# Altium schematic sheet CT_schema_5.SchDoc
size 309 x 315 mm
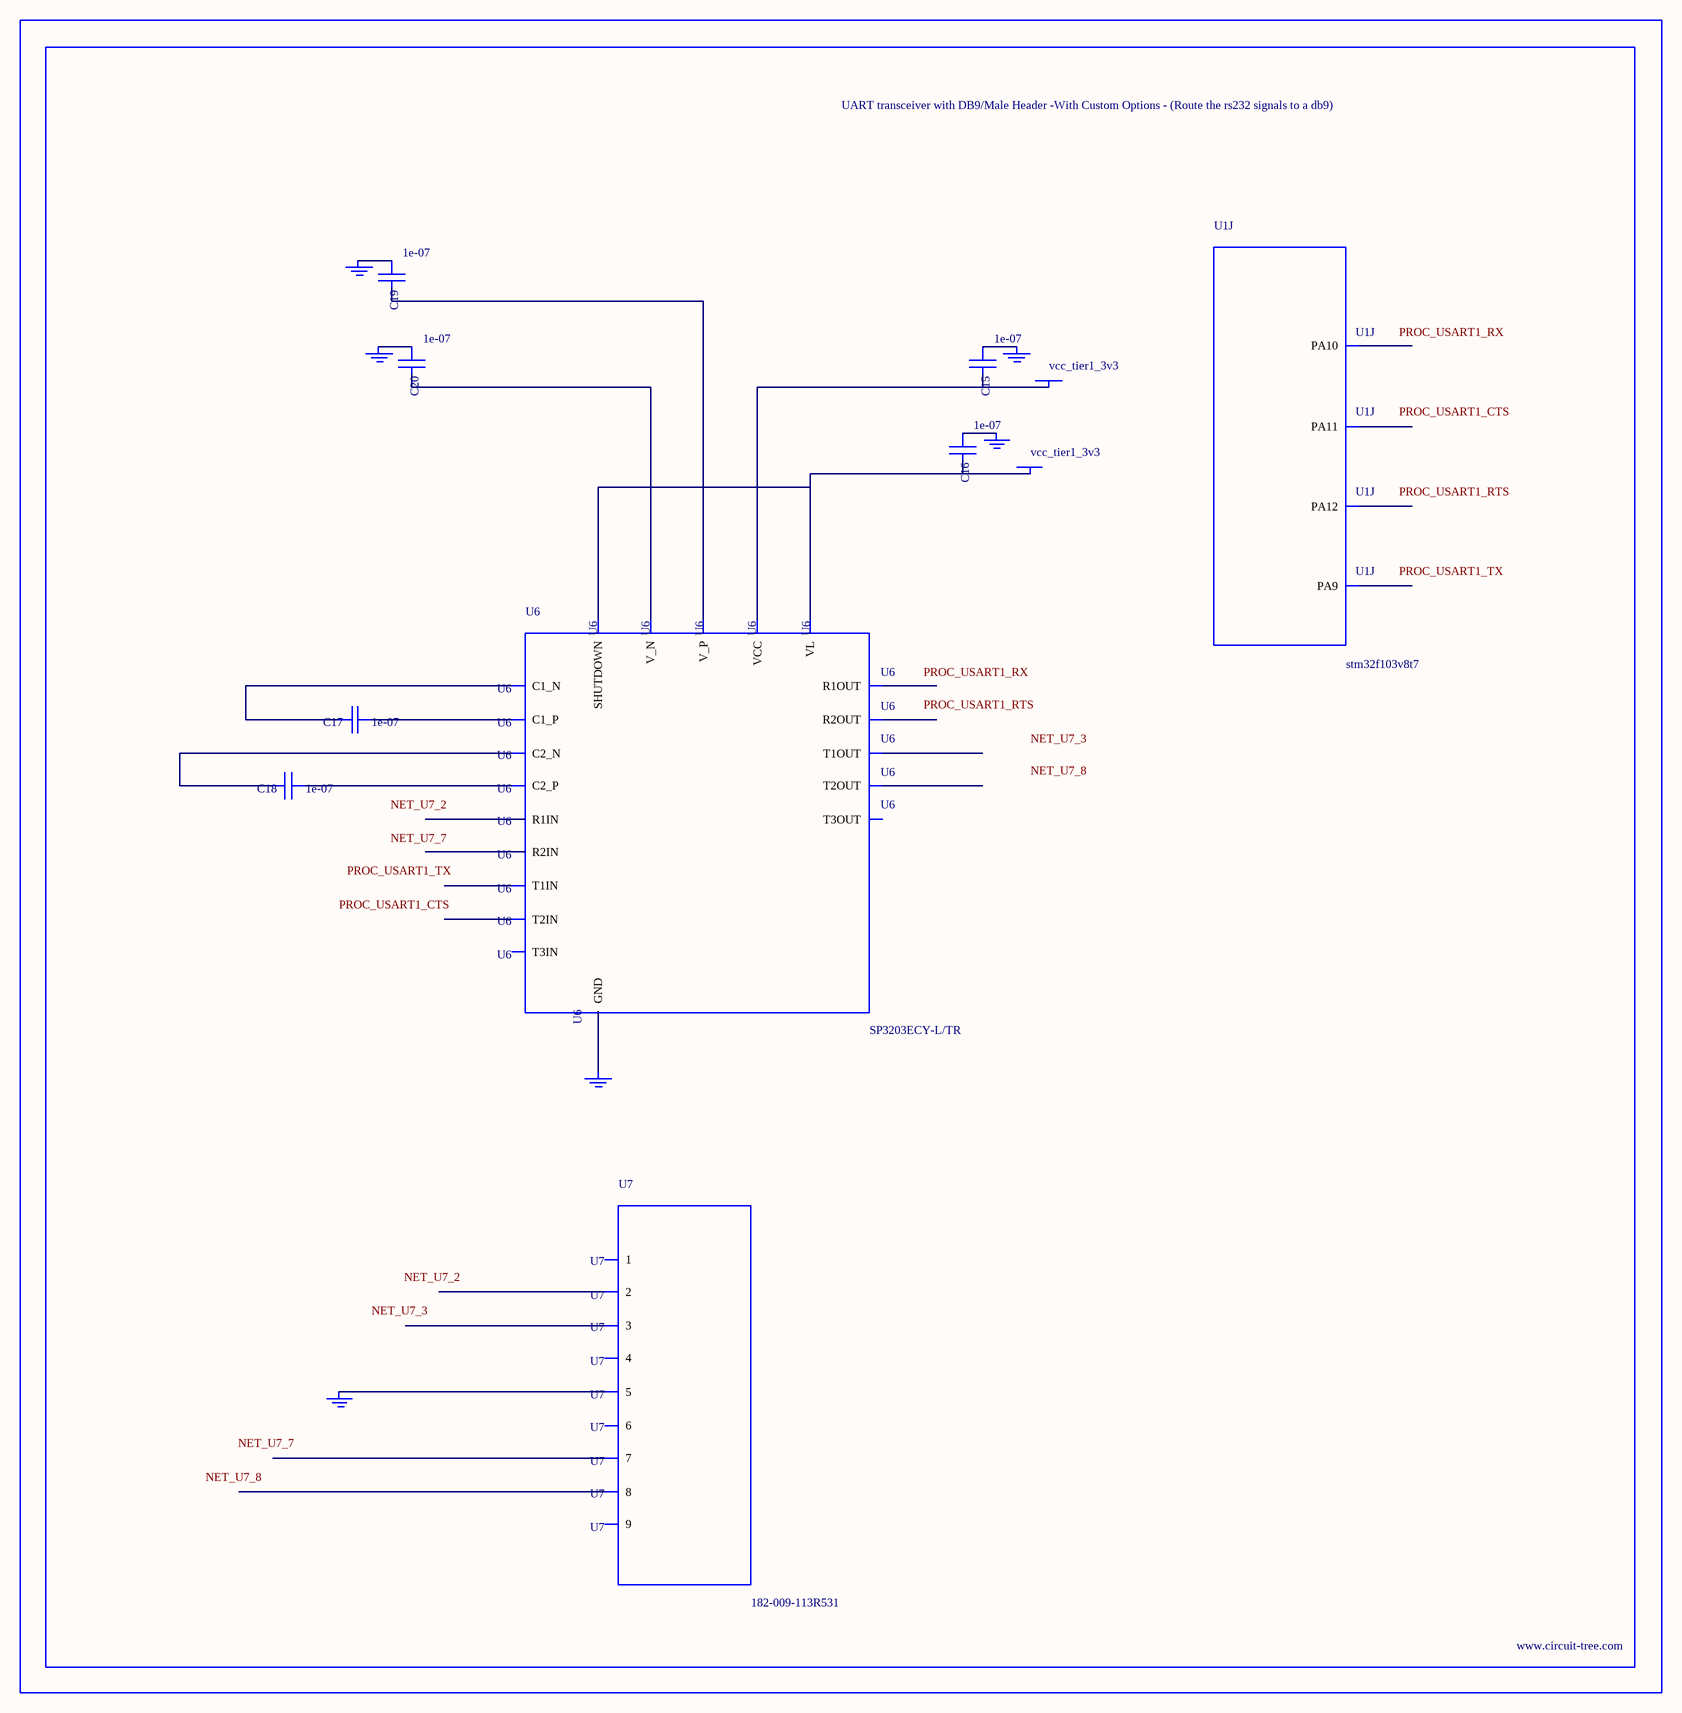
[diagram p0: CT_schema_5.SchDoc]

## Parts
BORDER4  (no value)
C15  1e-07  [C0402]
C16  1e-07  [C0402]
C17  1e-07  [C0402]
C18  1e-07  [C0402]
C19  1e-07  [C0402]
C20  1e-07  [C0402]
GND_INSTANCE_4_0  (no value)
GND_INSTANCE_4_1  (no value)
GND_INSTANCE_4_2  (no value)
GND_INSTANCE_4_3  (no value)
GND_INSTANCE_4_4  (no value)
GND_INSTANCE_4_5  (no value)
POWER_INSTANCE_4_0  vcc_tier1_3v3
POWER_INSTANCE_4_1  vcc_tier1_3v3
U1  stm32f103v8t7  [LQFP100]  (part J of 10)
U6  SP3203ECY-L/TR  [TSSOP20-I]
U7  182-009-113R531  [182-009-MALE]

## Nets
NetC15_1: C15.1 GND_INSTANCE_4_3.0(GND)
NetC15_2: C15.2 POWER_INSTANCE_4_1.0(PWR) U6.19(VCC)
NetC16_1: C16.1 GND_INSTANCE_4_2.0(GND)
NetC16_2: C16.2 POWER_INSTANCE_4_0.0(PWR) U6.12(VL) U6.20(SHUTDOWN)
NetC17_1: C17.1 U6.1(C1_P)
NetC17_2: C17.2 U6.3(C1_N)
NetC18_1: C18.1 U6.4(C2_P)
NetC18_2: C18.2 U6.5(C2_N)
NetC19_1: C19.1 GND_INSTANCE_4_0.0(GND)
NetC19_2: C19.2 U6.2(V_P)
NetC20_1: C20.1 GND_INSTANCE_4_1.0(GND)
NetC20_2: C20.2 U6.6(V_N)
NetGND_INSTANCE_4_4_0: GND_INSTANCE_4_4.0(GND) U6.18(GND)
NetGND_INSTANCE_4_5_0: GND_INSTANCE_4_5.0(GND) U7.5

Not connected (* = marked no-connect by the designer): U1 68(PA9) 69(PA10) 70(PA11) 71(PA12); U6 7(T1IN) 8(T2IN) 9(T3IN) 10(R2OUT) 11(R1OUT) 13(R2IN) 14(R1IN) 15(T3OUT) 16(T2OUT) 17(T1OUT); U7 1 2 3 4 6 7 8 9

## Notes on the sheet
- Labels drawn without touching a wire or pin: NET_U7_2, NET_U7_3, NET_U7_7, NET_U7_8, PROC_USART1_CTS, PROC_USART1_RTS, PROC_USART1_RX, PROC_USART1_TX

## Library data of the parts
BORDER4 = BORDER_PAGE4
C15-C20 = C0402C104K3RACTU
GND_INSTANCE_4_0-GND_INSTANCE_4_5 = GND
POWER_INSTANCE_4_0 POWER_INSTANCE_4_1 = PWR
